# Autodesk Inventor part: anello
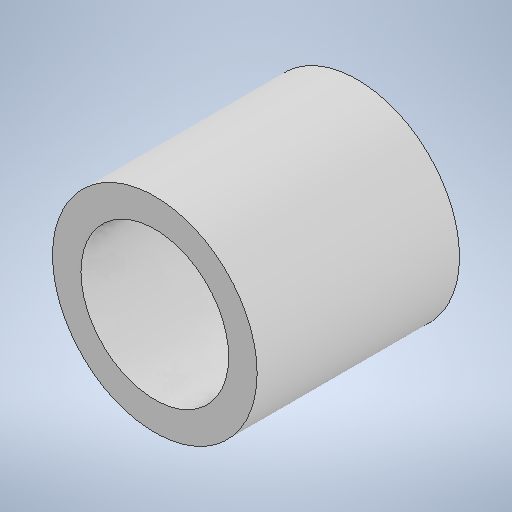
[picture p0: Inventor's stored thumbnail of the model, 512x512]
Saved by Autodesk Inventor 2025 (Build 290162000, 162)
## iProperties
Created: 2025-10
Part Number: anello
Material: Generico
Document SubType Name: Modeling
Designer: 18619647
Density: 1 g/cm^3
Appearance: Default
Author: 18619647
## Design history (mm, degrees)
sketch "Schizzo1"
  geometry: C1 r 9 at (0, 0); C2 r 6.5 at (0, 0); 1 further point
  constraints: 2 centre point, 2 coincident
  dimensions: "d0" = 18 diameter of C1; "d1" = 13 diameter of C2
extrude "Estrusione1" new body sketch "Schizzo1" distance "d2" = 17.8; taper "d3" = 0 deg
node "Solido1"
